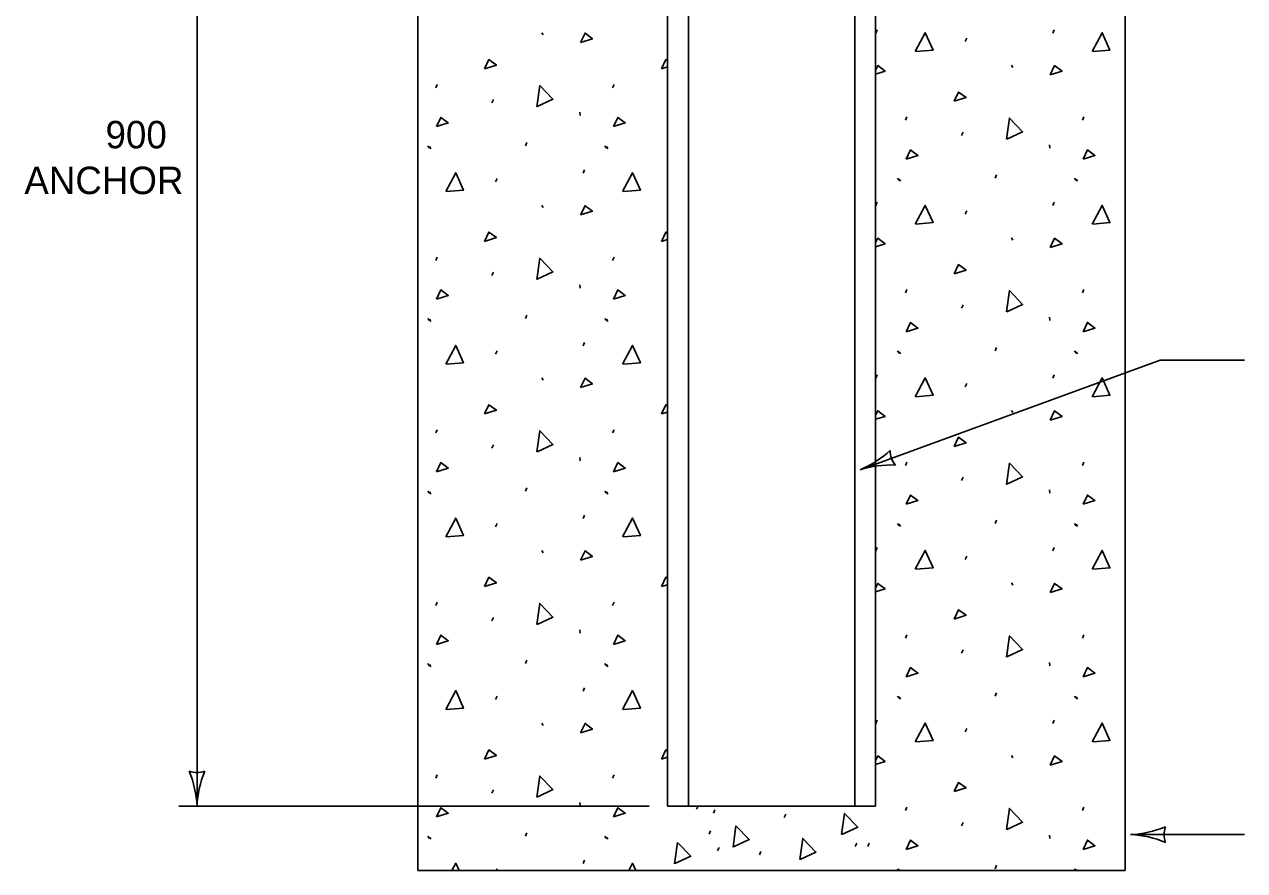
# Model space of a CAD drawing. Extents: x 49940 to 50043, y 49986 to 50011.
# Drawn here: x 50031.995 to 50034.661, y 49990.668 to 49992.517 of the extents above; entities that cross this region are included whole.
import ezdxf

# ---------------------------------------------------------------- set-up
doc = ezdxf.new("R2010")
doc.units = 0
for name, color, linetype in [('Level 1', 7, 'Continuous'), ('Level 2', 7, 'Continuous'), ('Level 3', 7, 'Continuous'), ('Level 4', 7, 'Continuous')]:
    doc.layers.add(name, color=color, linetype=linetype)

msp = doc.modelspace()

# ---------------------------------------------------------------- linework, layer by layer
at = {"layer": 'Level 1'}
for p, q in [((50033.3997, 49993.6432), (50033.3997, 49990.8091)), ((50033.8542, 49990.8091), (50033.8542, 49993.6432)), ((50032.8543, 49993.3952), (50032.8543, 49990.6682)), ((50034.3996, 49990.6682), (50034.3996, 49993.3952)), ((50033.8551, 49992.498), (50033.8584, 49992.5052)), ((50034.2419, 49992.498), (50034.245, 49992.5052)), ((50033.1251, 49992.4987), (50033.1285, 49992.4939)), ((50034.0505, 49992.4793), (50034.0537, 49992.4866)), ((50034.1514, 49992.4277), (50034.1546, 49992.4228)), ((50032.8935, 49992.3784), (50032.8967, 49992.3857)), ((50033.2801, 49992.3784), (50033.2835, 49992.3857)), ((50033.0162, 49992.3453), (50033.0194, 49992.3525)), ((50033.2082, 49992.325), (50033.2089, 49992.3177)), ((50033.9198, 49992.3074), (50033.9229, 49992.3147)), ((50034.3064, 49992.3074), (50034.3096, 49992.3147)), ((50034.0423, 49992.2744), (50034.0457, 49992.2816)), ((50032.8765, 49992.2516), (50032.8799, 49992.2468)), ((50032.8799, 49992.2498), (50032.883, 49992.245)), ((50033.0897, 49992.2516), (50033.0929, 49992.2589)), ((50033.2632, 49992.2516), (50033.2665, 49992.2468)), ((50033.2665, 49992.2498), (50033.2697, 49992.245)), ((50034.2343, 49992.2541), (50034.2352, 49992.2468)), ((50033.0242, 49992.1733), (50033.0276, 49992.1806)), ((50033.2156, 49992.1918), (50033.2188, 49992.1991)), ((50033.9028, 49992.1807), (50033.906, 49992.1759)), ((50034.1158, 49992.1807), (50034.1191, 49992.188)), ((50034.2894, 49992.1807), (50034.2926, 49992.1759)), ((50033.906, 49992.1789), (50033.9092, 49992.1741)), ((50034.2926, 49992.1789), (50034.2959, 49992.1741)), ((50033.8551, 49992.1209), (50033.8584, 49992.1282)), ((50034.2419, 49992.1209), (50034.245, 49992.1282)), ((50033.1251, 49992.1216), (50033.1285, 49992.1168)), ((50034.0505, 49992.1023), (50034.0537, 49992.1095)), ((50034.1514, 49992.0506), (50034.1546, 49992.0457)), ((50032.8935, 49992.0014), (50032.8967, 49992.0086)), ((50033.2801, 49992.0014), (50033.2835, 49992.0086)), ((50033.0162, 49991.9682), (50033.0194, 49991.9755)), ((50033.2082, 49991.9479), (50033.2089, 49991.9408)), ((50033.9198, 49991.9305), (50033.9229, 49991.9377)), ((50034.3064, 49991.9305), (50034.3096, 49991.9377)), ((50034.0423, 49991.8973), (50034.0457, 49991.9045)), ((50032.8765, 49991.8746), (50032.8799, 49991.8697)), ((50032.8799, 49991.8727), (50032.883, 49991.8679)), ((50033.0897, 49991.8746), (50033.0929, 49991.8818)), ((50033.2632, 49991.8746), (50033.2665, 49991.8697)), ((50033.2665, 49991.8727), (50033.2697, 49991.8679)), ((50034.2343, 49991.877), (50034.2352, 49991.8697)), ((50033.2156, 49991.8147), (50033.2188, 49991.822)), ((50034.1158, 49991.8037), (50034.1191, 49991.8109)), ((50033.0242, 49991.7962), (50033.0276, 49991.8035)), ((50033.9028, 49991.8037), (50033.906, 49991.7988)), ((50033.906, 49991.8018), (50033.9092, 49991.797)), ((50034.2894, 49991.8037), (50034.2926, 49991.7988)), ((50034.2926, 49991.8018), (50034.2959, 49991.797)), ((50033.1251, 49991.7446), (50033.1285, 49991.7397)), ((50033.8551, 49991.7438), (50033.8584, 49991.7511)), ((50034.0505, 49991.7253), (50034.0537, 49991.7326)), ((50034.2419, 49991.7438), (50034.245, 49991.7511)), ((50034.1514, 49991.6737), (50034.1546, 49991.6688)), ((50032.8935, 49991.6243), (50032.8967, 49991.6315)), ((50033.2801, 49991.6243), (50033.2835, 49991.6315)), ((50033.0162, 49991.5911), (50033.0194, 49991.5984)), ((50033.2082, 49991.5709), (50033.2089, 49991.5637)), ((50033.9198, 49991.5534), (50033.9229, 49991.5606)), ((50034.3064, 49991.5534), (50034.3096, 49991.5606)), ((50034.0423, 49991.5202), (50034.0457, 49991.5275)), ((50032.8765, 49991.4975), (50032.8799, 49991.4926)), ((50032.8799, 49991.4957), (50032.883, 49991.4908)), ((50033.0897, 49991.4975), (50033.0929, 49991.5047)), ((50033.2632, 49991.4975), (50033.2665, 49991.4926)), ((50033.2665, 49991.4957), (50033.2697, 49991.4908)), ((50034.2343, 49991.4999), (50034.2352, 49991.4926)), ((50033.2156, 49991.4376), (50033.2188, 49991.4449)), ((50034.1158, 49991.4266), (50034.1191, 49991.4338)), ((50033.0242, 49991.4191), (50033.0276, 49991.4264)), ((50033.9028, 49991.4266), (50033.906, 49991.4217)), ((50033.906, 49991.4247), (50033.9092, 49991.4199)), ((50034.2894, 49991.4266), (50034.2926, 49991.4217)), ((50034.2926, 49991.4247), (50034.2959, 49991.4199)), ((50033.1251, 49991.3675), (50033.1285, 49991.3626)), ((50033.8551, 49991.3667), (50033.8584, 49991.374)), ((50034.0505, 49991.3482), (50034.0537, 49991.3555)), ((50034.2419, 49991.3667), (50034.245, 49991.374)), ((50034.1514, 49991.2966), (50034.1546, 49991.2917)), ((50032.8935, 49991.2472), (50032.8967, 49991.2545)), ((50033.2801, 49991.2472), (50033.2835, 49991.2545)), ((50033.0162, 49991.2142), (50033.0194, 49991.2213)), ((50033.2082, 49991.1939), (50033.2089, 49991.1866)), ((50033.9198, 49991.1763), (50033.9229, 49991.1836)), ((50034.3064, 49991.1763), (50034.3096, 49991.1836)), ((50034.0423, 49991.1431), (50034.0457, 49991.1504)), ((50032.8765, 49991.1204), (50032.8799, 49991.1155)), ((50032.8799, 49991.1186), (50032.883, 49991.1137)), ((50033.0897, 49991.1204), (50033.0929, 49991.1277)), ((50033.2632, 49991.1204), (50033.2665, 49991.1155)), ((50033.2665, 49991.1186), (50033.2697, 49991.1137)), ((50034.2343, 49991.1228), (50034.2352, 49991.1157)), ((50033.2156, 49991.0605), (50033.2188, 49991.0678)), ((50033.0242, 49991.0421), (50033.0276, 49991.0493)), ((50033.9028, 49991.0495), (50033.906, 49991.0446)), ((50033.906, 49991.0477), (50033.9092, 49991.0428)), ((50034.1158, 49991.0495), (50034.1191, 49991.0568)), ((50034.2894, 49991.0495), (50034.2926, 49991.0446)), ((50034.2926, 49991.0477), (50034.2959, 49991.0428)), ((50033.1251, 49990.9904), (50033.1285, 49990.9855)), ((50033.8551, 49990.9896), (50033.8584, 49990.9969)), ((50034.2419, 49990.9896), (50034.245, 49990.9969)), ((50034.0505, 49990.9712), (50034.0537, 49990.9784)), ((50034.1514, 49990.9195), (50034.1546, 49990.9146)), ((50032.8935, 49990.8701), (50032.8967, 49990.8774)), ((50033.2801, 49990.8701), (50033.2835, 49990.8774)), ((50033.0162, 49990.8371), (50033.0194, 49990.8444)), ((50033.2082, 49990.8168), (50033.2089, 49990.8095)), ((50033.3997, 49990.8091), (50033.8542, 49990.8091)), ((50033.4636, 49990.8024), (50033.4669, 49990.8097)), ((50033.5001, 49990.7933), (50033.5034, 49990.8006)), ((50033.9198, 49990.7992), (50033.9229, 49990.8065)), ((50034.3064, 49990.7992), (50034.3096, 49990.8065)), ((50033.6552, 49990.7842), (50033.6584, 49990.7915)), ((50034.0423, 49990.766), (50034.0457, 49990.7733)), ((50032.8765, 49990.7435), (50032.8799, 49990.7386)), ((50032.8799, 49990.7415), (50032.883, 49990.7366)), ((50033.0897, 49990.7435), (50033.0929, 49990.7507)), ((50033.2632, 49990.7435), (50033.2665, 49990.7386)), ((50033.2665, 49990.7415), (50033.2697, 49990.7366)), ((50033.491, 49990.7478), (50033.4942, 49990.7551)), ((50034.2343, 49990.7459), (50034.2352, 49990.7386)), ((50033.5093, 49990.7115), (50033.5125, 49990.7188)), ((50033.8102, 49990.7206), (50033.8136, 49990.7278)), ((50033.8376, 49990.7206), (50033.8408, 49990.7278)), ((50033.2156, 49990.6836), (50033.2188, 49990.6909)), ((50033.6006, 49990.7024), (50033.6037, 49990.7097)), ((50032.8543, 49990.6682), (50033.3997, 49990.6682)), ((50033.0256, 49990.6682), (50033.0276, 49990.6722)), ((50033.3997, 49990.6682), (50033.8542, 49990.6682)), ((50033.8542, 49990.6682), (50034.3996, 49990.6682)), ((50033.9028, 49990.6724), (50033.9057, 49990.6682)), ((50033.906, 49990.6706), (50033.9076, 49990.6682)), ((50034.1158, 49990.6724), (50034.1191, 49990.6797)), ((50034.2894, 49990.6724), (50034.2923, 49990.6682)), ((50034.2926, 49990.6706), (50034.2943, 49990.6682))]:
    msp.add_line(p, q, dxfattribs=at)
for points in [[(50033.21, 49992.4777), (50033.2197, 49992.4978), (50033.2357, 49992.4857), (50033.21, 49992.4777)], [(50033.9414, 49992.4575), (50033.9632, 49992.4987), (50033.9802, 49992.4609), (50033.9423, 49992.4575)], [(50034.3282, 49992.4575), (50034.35, 49992.4987), (50034.3668, 49992.4609), (50034.329, 49992.4575)], [(50033.0002, 49992.42), (50033.0099, 49992.4401), (50033.0261, 49992.428), (50033.0002, 49992.42)], [(50033.3869, 49992.42), (50033.3966, 49992.4401), (50033.3997, 49992.4378)], [(50033.3997, 49992.4239), (50033.3869, 49992.42)], [(50033.8542, 49992.4165), (50033.8592, 49992.4269), (50033.8752, 49992.4148), (50033.8542, 49992.4081)], [(50034.2361, 49992.4068), (50034.2458, 49992.4269), (50034.262, 49992.4148), (50034.2361, 49992.4068)], [(50033.1144, 49992.3369), (50033.1208, 49992.3831), (50033.1497, 49992.3533), (50033.1151, 49992.3372)], [(50034.0264, 49992.3491), (50034.0361, 49992.3692), (50034.0522, 49992.3571), (50034.0264, 49992.3491)], [(50032.8952, 49992.2936), (50032.9049, 49992.3138), (50032.9209, 49992.3016), (50032.8952, 49992.2936)], [(50033.2818, 49992.2936), (50033.2915, 49992.3138), (50033.3077, 49992.3016), (50033.2818, 49992.2936)], [(50034.1406, 49992.266), (50034.147, 49992.3121), (50034.1759, 49992.2822), (50034.1414, 49992.2663)], [(50033.9213, 49992.2227), (50033.931, 49992.2428), (50033.9472, 49992.2307), (50033.9213, 49992.2227)], [(50034.3081, 49992.2227), (50034.3176, 49992.2428), (50034.3338, 49992.2307), (50034.3081, 49992.2227)], [(50032.9153, 49992.1515), (50032.9371, 49992.1927), (50032.9541, 49992.1547), (50032.9161, 49992.1515)], [(50033.3019, 49992.1515), (50033.3238, 49992.1927), (50033.3407, 49992.1547), (50033.3029, 49992.1515)], [(50033.21, 49992.1006), (50033.2197, 49992.1207), (50033.2357, 49992.1086), (50033.21, 49992.1006)], [(50033.9414, 49992.0806), (50033.9632, 49992.1216), (50033.9802, 49992.0838), (50033.9423, 49992.0806)], [(50034.3282, 49992.0806), (50034.35, 49992.1216), (50034.3668, 49992.0838), (50034.329, 49992.0806)], [(50033.0002, 49992.0429), (50033.0099, 49992.063), (50033.0261, 49992.051), (50033.0002, 49992.0429)], [(50033.3869, 49992.0429), (50033.3966, 49992.063), (50033.3997, 49992.0607)], [(50033.3997, 49992.047), (50033.3869, 49992.0429)], [(50033.8542, 49992.0394), (50033.8592, 49992.0498), (50033.8752, 49992.0377), (50033.8542, 49992.0312)], [(50034.2361, 49992.0297), (50034.2458, 49992.0498), (50034.262, 49992.0377), (50034.2361, 49992.0297)], [(50033.1144, 49991.9598), (50033.1208, 49992.0061), (50033.1497, 49991.9762), (50033.1151, 49991.9601)], [(50034.0264, 49991.972), (50034.0361, 49991.9921), (50034.0522, 49991.98), (50034.0264, 49991.972)], [(50032.8952, 49991.9165), (50032.9049, 49991.9368), (50032.9209, 49991.9247), (50032.8952, 49991.9165)], [(50033.2818, 49991.9165), (50033.2915, 49991.9368), (50033.3077, 49991.9247), (50033.2818, 49991.9165)], [(50034.1406, 49991.8889), (50034.147, 49991.9352), (50034.1759, 49991.9052), (50034.1414, 49991.8892)], [(50033.9213, 49991.8456), (50033.931, 49991.8658), (50033.9472, 49991.8536), (50033.9213, 49991.8456)], [(50034.3081, 49991.8456), (50034.3176, 49991.8658), (50034.3338, 49991.8536), (50034.3081, 49991.8456)], [(50032.9153, 49991.7744), (50032.9371, 49991.8156), (50032.9541, 49991.7776), (50032.9161, 49991.7744)], [(50033.3019, 49991.7744), (50033.3238, 49991.8156), (50033.3407, 49991.7776), (50033.3029, 49991.7744)], [(50033.21, 49991.7235), (50033.2197, 49991.7437), (50033.2357, 49991.7315), (50033.21, 49991.7235)], [(50033.9414, 49991.7035), (50033.9632, 49991.7446), (50033.9802, 49991.7067), (50033.9423, 49991.7035)], [(50034.3282, 49991.7035), (50034.35, 49991.7446), (50034.3668, 49991.7067), (50034.329, 49991.7035)], [(50033.0002, 49991.6658), (50033.0099, 49991.6861), (50033.0261, 49991.674), (50033.0002, 49991.6658)], [(50033.3869, 49991.6658), (50033.3966, 49991.6861), (50033.3997, 49991.6837)], [(50033.3997, 49991.6699), (50033.3869, 49991.6658)], [(50033.8542, 49991.6623), (50033.8592, 49991.6728), (50033.8752, 49991.6606), (50033.8542, 49991.6541)], [(50034.2361, 49991.6526), (50034.2458, 49991.6728), (50034.262, 49991.6606), (50034.2361, 49991.6526)], [(50033.1144, 49991.5828), (50033.1208, 49991.629), (50033.1497, 49991.5991), (50033.1151, 49991.5831)], [(50034.0264, 49991.5949), (50034.0361, 49991.615), (50034.0522, 49991.6029), (50034.0264, 49991.5949)], [(50032.8952, 49991.5394), (50032.9049, 49991.5597), (50032.9209, 49991.5476), (50032.8952, 49991.5394)], [(50033.2818, 49991.5394), (50033.2915, 49991.5597), (50033.3077, 49991.5476), (50033.2818, 49991.5394)], [(50034.1406, 49991.5119), (50034.147, 49991.5581), (50034.1759, 49991.5282), (50034.1414, 49991.5122)], [(50033.9213, 49991.4685), (50033.931, 49991.4887), (50033.9472, 49991.4766), (50033.9213, 49991.4685)], [(50034.3081, 49991.4685), (50034.3176, 49991.4887), (50034.3338, 49991.4766), (50034.3081, 49991.4685)], [(50032.9153, 49991.3973), (50032.9371, 49991.4385), (50032.9541, 49991.4005), (50032.9161, 49991.3973)], [(50033.3019, 49991.3973), (50033.3238, 49991.4385), (50033.3407, 49991.4005), (50033.3029, 49991.3973)], [(50033.21, 49991.3464), (50033.2197, 49991.3667), (50033.2357, 49991.3546), (50033.21, 49991.3464)], [(50033.9414, 49991.3264), (50033.9632, 49991.3676), (50033.9802, 49991.3296), (50033.9423, 49991.3264)], [(50034.3282, 49991.3264), (50034.35, 49991.3676), (50034.3668, 49991.3296), (50034.329, 49991.3264)], [(50033.0002, 49991.2887), (50033.0099, 49991.309), (50033.0261, 49991.2969), (50033.0002, 49991.2887)], [(50033.3869, 49991.2887), (50033.3966, 49991.309), (50033.3997, 49991.3067)], [(50033.3997, 49991.2928), (50033.3869, 49991.2887)], [(50033.8542, 49991.2852), (50033.8592, 49991.2957), (50033.8752, 49991.2836), (50033.8542, 49991.277)], [(50034.2361, 49991.2755), (50034.2458, 49991.2957), (50034.262, 49991.2836), (50034.2361, 49991.2755)], [(50033.1144, 49991.2057), (50033.1208, 49991.2519), (50033.1497, 49991.222), (50033.1151, 49991.206)], [(50034.0264, 49991.2178), (50034.0361, 49991.2379), (50034.0522, 49991.226), (50034.0264, 49991.2178)], [(50032.8952, 49991.1625), (50032.9049, 49991.1827), (50032.9209, 49991.1705), (50032.8952, 49991.1625)], [(50033.2818, 49991.1625), (50033.2915, 49991.1827), (50033.3077, 49991.1705), (50033.2818, 49991.1625)], [(50034.1406, 49991.1348), (50034.147, 49991.181), (50034.1759, 49991.1511), (50034.1414, 49991.1351)], [(50033.9213, 49991.0914), (50033.931, 49991.1117), (50033.9472, 49991.0996), (50033.9213, 49991.0914)], [(50034.3081, 49991.0914), (50034.3176, 49991.1117), (50034.3338, 49991.0996), (50034.3081, 49991.0914)], [(50032.9153, 49991.0202), (50032.9371, 49991.0615), (50032.9541, 49991.0234), (50032.9161, 49991.0202)], [(50033.3019, 49991.0202), (50033.3238, 49991.0615), (50033.3407, 49991.0234), (50033.3029, 49991.0202)], [(50033.21, 49990.9693), (50033.2197, 49990.9896), (50033.2357, 49990.9775), (50033.21, 49990.9693)], [(50033.9414, 49990.9493), (50033.9632, 49990.9905), (50033.9802, 49990.9525), (50033.9423, 49990.9493)], [(50034.3282, 49990.9493), (50034.35, 49990.9905), (50034.3668, 49990.9525), (50034.329, 49990.9493)], [(50033.0002, 49990.9118), (50033.0099, 49990.9319), (50033.0261, 49990.9198), (50033.0002, 49990.9118)], [(50033.3869, 49990.9118), (50033.3966, 49990.9319), (50033.3997, 49990.9296)], [(50033.3997, 49990.9157), (50033.3869, 49990.9118)], [(50033.8542, 49990.9083), (50033.8592, 49990.9186), (50033.8752, 49990.9066), (50033.8542, 49990.9)], [(50034.2361, 49990.8984), (50034.2458, 49990.9186), (50034.262, 49990.9066), (50034.2361, 49990.8984)], [(50033.1144, 49990.8286), (50033.1208, 49990.8748), (50033.1497, 49990.845), (50033.1151, 49990.8289)], [(50034.0264, 49990.8407), (50034.0361, 49990.861), (50034.0522, 49990.8489), (50034.0264, 49990.8407)], [(50032.8952, 49990.7854), (50032.9049, 49990.8056), (50032.9209, 49990.7934), (50032.8952, 49990.7854)], [(50033.2818, 49990.7854), (50033.2915, 49990.8056), (50033.3077, 49990.7934), (50033.2818, 49990.7854)], [(50034.1406, 49990.7577), (50034.147, 49990.8039), (50034.1759, 49990.7741), (50034.1414, 49990.758)], [(50033.7804, 49990.7469), (50033.7867, 49990.793), (50033.8157, 49990.7631), (50033.7811, 49990.7471)], [(50033.5431, 49990.7197), (50033.5495, 49990.7657), (50033.5784, 49990.7359), (50033.5439, 49990.7198)], [(50033.4154, 49990.6833), (50033.4218, 49990.7294), (50033.4507, 49990.6995), (50033.4162, 49990.6836)], [(50033.689, 49990.6924), (50033.6955, 49990.7385), (50033.7243, 49990.7086), (50033.6898, 49990.6927)], [(50033.9213, 49990.7144), (50033.931, 49990.7347), (50033.9472, 49990.7225), (50033.9213, 49990.7144)], [(50034.3081, 49990.7144), (50034.3176, 49990.7347), (50034.3338, 49990.7225), (50034.3081, 49990.7144)], [(50032.9285, 49990.6682), (50032.9371, 49990.6844), (50032.9444, 49990.6682)], [(50033.3151, 49990.6682), (50033.3238, 49990.6844), (50033.331, 49990.6682)]]:
    msp.add_lwpolyline(points, dxfattribs=at)
at = {"layer": 'Level 3'}
for p, q in [((50032.3719, 49993.6432), (50032.3719, 49990.8091)), ((50033.8207, 49991.5434), (50034.4764, 49991.7833)), ((50034.4764, 49991.7833), (50034.6609, 49991.7833)), ((50033.3597, 49990.8091), (50032.3319, 49990.8091)), ((50034.4118, 49990.7467), (50034.6609, 49990.7467))]:
    msp.add_line(p, q, dxfattribs=at)
for centre, radius, start, end in [((50033.7298, 49991.7584), 0.233, 292.9301, 312.1799), ((50033.941, 49991.5879), 0.0548, 182.2416, 217.964), ((50033.8883, 49991.3321), 0.2223, 87.5588, 107.7423), ((50032.3719, 49990.9373), 0.0548, 252.1388, 287.8612), ((50032.1392, 49990.7976), 0.233, 2.8273, 22.0772), ((50032.594, 49990.7999), 0.2223, 157.456, 177.6395), ((50034.4003, 49990.9794), 0.233, 272.8273, 292.0772), ((50034.4027, 49990.5246), 0.2223, 67.456, 87.6395), ((50034.54, 49990.7467), 0.0548, 162.1388, 197.8612)]:
    msp.add_arc(centre, radius, start, end, dxfattribs=at)
at = {"layer": 'Level 4'}
for p, q in [((50033.4457, 49990.8091), (50033.4457, 49993.6432)), ((50033.8093, 49990.8091), (50033.8093, 49993.6432))]:
    msp.add_line(p, q, dxfattribs=at)

# ---------------------------------------------------------------- texts
at = {"layer": 'Level 2'}
for s, p in [('900', (50032.172, 49992.2461)), ('ANCHOR', (50031.9946, 49992.1461))]:
    msp.add_text(s, height=0.06, dxfattribs=at).set_placement(p)

doc.saveas('drawing.dxf')
